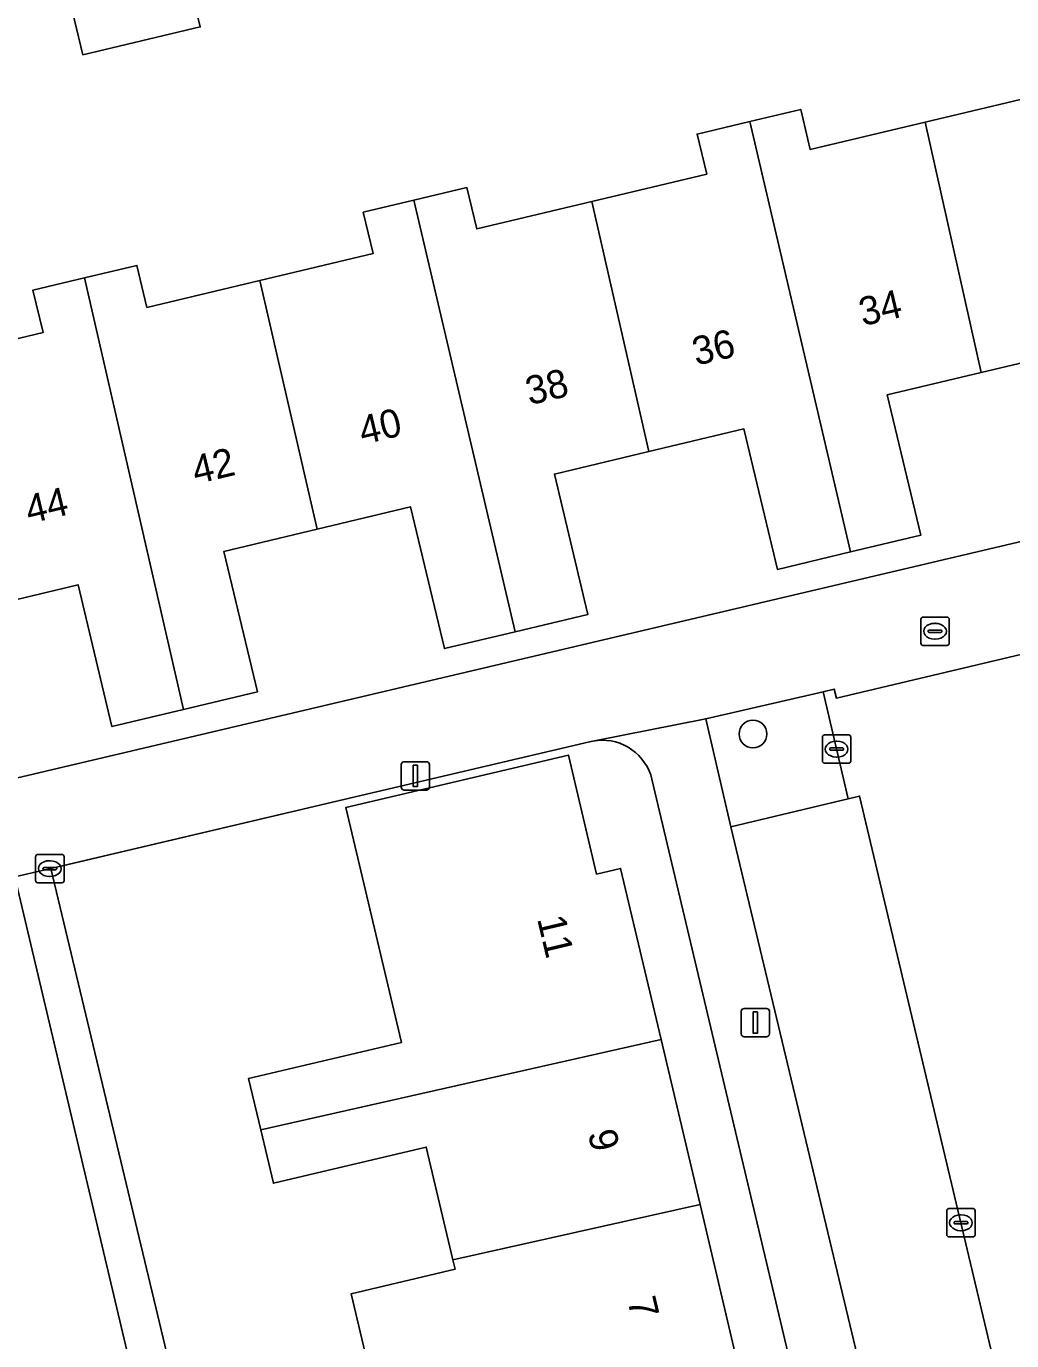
# Model space of a CAD drawing. Extents: x 158031 to 159244, y 380104 to 381214.
# Drawn here: x 158383.81 to 158418.58, y 380885.43 to 380931.84 of the extents above; entities that cross this region are included whole.
import ezdxf

# ---------------------------------------------------------------- set-up
doc = ezdxf.new("R2010")
doc.units = 0
for name, color, linetype in [('IMGEO_Boom', 7, 'Continuous'), ('IMGEO_Erf', 7, 'Continuous'), ('IMGEO_Groenvoorziening', 7, 'Continuous'), ('IMGEO_Kolk', 7, 'Continuous'), ('IMGEO_Lichtmast', 7, 'Continuous'), ('IMGEO_Muur', 7, 'Continuous'), ('IMGEO_Pand', 7, 'Continuous'), ('IMGEO_Pand_nummerreeks', 7, 'Continuous'), ('IMGEO_Parkeervlak_open', 7, 'Continuous'), ('IMGEO_Rijbaan_lokaal_open', 7, 'Continuous'), ('IMGEO_Rioolput', 7, 'Continuous'), ('IMGEO_Voetpad_open', 7, 'Continuous')]:
    doc.layers.add(name, color=color, linetype=linetype)

msp = doc.modelspace()

# ---------------------------------------------------------------- linework, layer by layer
at = {"layer": 'IMGEO_Boom'}
msp.add_circle((158409.446, 380906.85), 0.489, dxfattribs=at)
at = {"layer": 'IMGEO_Erf'}
msp.add_lwpolyline([(158385.8, 380930.828), (158385.214, 380933.284), (158389.357, 380934.271), (158389.942, 380931.815)], close=True, dxfattribs=at)
for points in [[(158380.362, 380920.062), (158384.397, 380921.024), (158384.04, 380922.522), (158385.859, 380922.955), (158387.708, 380923.396), (158388.061, 380921.914), (158392.049, 380922.864), (158396.041, 380923.815), (158395.694, 380925.272), (158397.483, 380925.698), (158399.355, 380926.144), (158399.703, 380924.684), (158403.762, 380925.651), (158407.815, 380926.617), (158407.478, 380928.032), (158409.334, 380928.474), (158411.133, 380928.903), (158411.471, 380927.486), (158415.526, 380928.452), (158419.584, 380929.419)], [(158420.824, 380920.408), (158417.502, 380919.616), (158414.185, 380918.826), (158415.366, 380913.868), (158412.889, 380913.278), (158410.309, 380912.663), (158409.128, 380917.62), (158405.771, 380916.82), (158402.444, 380916.027), (158403.625, 380911.072), (158401.054, 380910.459), (158398.557, 380909.864), (158397.364, 380914.868), (158394.068, 380914.082), (158390.781, 380913.299), (158391.963, 380908.338), (158389.354, 380907.717), (158386.828, 380907.115), (158385.635, 380912.121), (158382.383, 380911.346)], [(158371.904, 380902.569), (158443.778, 380919.513)], [(158414.344, 380869.537), (158405.883, 380905.251), (158405.838, 380905.406), (158405.78, 380905.556), (158405.708, 380905.701), (158405.624, 380905.838), (158405.528, 380905.967), (158405.421, 380906.088), (158405.303, 380906.198), (158405.176, 380906.297), (158405.041, 380906.385), (158404.898, 380906.46), (158404.749, 380906.522), (158404.596, 380906.57), (158404.438, 380906.605), (158404.278, 380906.625), (158404.117, 380906.631), (158403.956, 380906.623), (158403.797, 380906.6), (158403.676, 380906.573), (158395.014, 380904.536), (158384.676, 380902.106), (158392.784, 380868.149)], [(158396.132, 380883.458), (158395.274, 380887.088), (158398.935, 380887.953), (158398.856, 380888.287), (158397.916, 380892.265), (158392.524, 380890.99), (158392.078, 380892.879), (158391.65, 380894.688), (158397.04, 380895.962), (158395.081, 380904.254), (158402.935, 380906.109), (158403.928, 380901.906), (158404.777, 380902.106), (158406.205, 380896.065), (158407.583, 380890.235), (158408.966, 380884.383)], [(158388.286, 380881.153), (158383.406, 380901.807)]]:
    msp.add_lwpolyline(points, dxfattribs=at)
at = {"layer": 'IMGEO_Groenvoorziening'}
msp.add_lwpolyline([(158411.93, 380908.345), (158407.779, 380907.39), (158408.671, 380903.573), (158412.805, 380904.563)], close=True, dxfattribs=at)
at = {"layer": 'IMGEO_Kolk'}
for p, q in [((158411.898, 380905.891), (158411.898, 380906.743)), ((158411.973, 380906.817), (158412.825, 380906.817)), ((158412.386, 380906.597), (158412.411, 380906.597)), ((158412.899, 380906.743), (158412.899, 380905.891)), ((158412.157, 380906.311), (158412.157, 380906.323)), ((158412.595, 380906.274), (158412.197, 380906.274)), ((158412.2, 380906.36), (158412.598, 380906.36)), ((158412.641, 380906.323), (158412.641, 380906.311)), ((158412.825, 380905.817), (158411.973, 380905.817)), ((158412.409, 380906.037), (158412.384, 380906.037)), ((158384.136, 380901.671), (158384.136, 380902.523)), ((158384.211, 380902.597), (158385.063, 380902.597)), ((158384.624, 380902.377), (158384.649, 380902.377)), ((158385.137, 380902.523), (158385.137, 380901.671)), ((158384.395, 380902.091), (158384.395, 380902.103)), ((158384.833, 380902.054), (158384.435, 380902.054)), ((158384.438, 380902.14), (158384.836, 380902.14)), ((158384.879, 380902.103), (158384.879, 380902.091)), ((158385.063, 380901.597), (158384.211, 380901.597)), ((158384.647, 380901.817), (158384.622, 380901.817)), ((158416.285, 380889.169), (158416.285, 380890.021)), ((158416.36, 380890.095), (158417.212, 380890.095)), ((158416.773, 380889.875), (158416.798, 380889.875)), ((158417.286, 380890.021), (158417.286, 380889.169)), ((158416.544, 380889.589), (158416.544, 380889.601)), ((158416.982, 380889.552), (158416.584, 380889.552)), ((158416.587, 380889.638), (158416.985, 380889.638)), ((158417.028, 380889.601), (158417.028, 380889.589)), ((158417.212, 380889.095), (158416.36, 380889.095)), ((158416.796, 380889.315), (158416.771, 380889.315))]:
    msp.add_line(p, q, dxfattribs=at)
for points in [[(158411.898, 380905.891), (158411.898, 380906.743)], [(158411.973, 380906.817), (158412.825, 380906.817)], [(158412.899, 380906.743), (158412.899, 380905.891)], [(158412.825, 380905.817), (158411.973, 380905.817)], [(158384.136, 380901.671), (158384.136, 380902.523)], [(158384.211, 380902.597), (158385.063, 380902.597)], [(158385.137, 380902.523), (158385.137, 380901.671)], [(158385.063, 380901.597), (158384.211, 380901.597)], [(158416.285, 380889.169), (158416.285, 380890.021)], [(158416.36, 380890.095), (158417.212, 380890.095)], [(158417.286, 380890.021), (158417.286, 380889.169)], [(158417.212, 380889.095), (158416.36, 380889.095)]]:
    msp.add_lwpolyline(points, dxfattribs=at)
for centre, radius, start, end in [((158411.975, 380906.741), 0.0765, 91.552, 178.448), ((158411.975, 380906.741), 0.0765, 91.552, 178.448), ((158412.823, 380906.741), 0.0765, 1.552, 88.448), ((158412.823, 380906.741), 0.0765, 1.552, 88.448), ((158412.197, 380906.32), 0.0403, 85.8775, 175.7526), ((158412.194, 380906.31), 0.0366, 178.938, 274.7102), ((158412.598, 380906.317), 0.043, 264.8664, 352.4533), ((158412.602, 380906.322), 0.0386, 1.7309, 96.639), ((158411.975, 380905.893), 0.0765, 181.552, 268.448), ((158411.975, 380905.893), 0.0765, 181.552, 268.448), ((158412.823, 380905.893), 0.0765, 271.552, 358.448), ((158412.823, 380905.893), 0.0765, 271.552, 358.448), ((158384.213, 380902.521), 0.0765, 91.552, 178.448), ((158384.213, 380902.521), 0.0765, 91.552, 178.448), ((158385.061, 380902.521), 0.0765, 1.552, 88.448), ((158385.061, 380902.521), 0.0765, 1.552, 88.448), ((158384.435, 380902.1), 0.0403, 85.8775, 175.7526), ((158384.432, 380902.09), 0.0366, 178.938, 274.7102), ((158384.836, 380902.097), 0.043, 264.8664, 352.4533), ((158384.84, 380902.102), 0.0386, 1.7309, 96.639), ((158384.213, 380901.673), 0.0765, 181.552, 268.448), ((158384.213, 380901.673), 0.0765, 181.552, 268.448), ((158385.061, 380901.673), 0.0765, 271.552, 358.448), ((158385.061, 380901.673), 0.0765, 271.552, 358.448), ((158416.362, 380890.019), 0.0765, 91.552, 178.448), ((158416.362, 380890.019), 0.0765, 91.552, 178.448), ((158417.21, 380890.019), 0.0765, 1.552, 88.448), ((158417.21, 380890.019), 0.0765, 1.552, 88.448), ((158416.584, 380889.598), 0.0403, 85.8775, 175.7526), ((158416.581, 380889.588), 0.0366, 178.938, 274.7102), ((158416.985, 380889.595), 0.043, 264.8664, 352.4533), ((158416.989, 380889.6), 0.0386, 1.7309, 96.639), ((158416.362, 380889.171), 0.0765, 181.552, 268.448), ((158416.362, 380889.171), 0.0765, 181.552, 268.448), ((158417.21, 380889.171), 0.0765, 271.552, 358.448), ((158417.21, 380889.171), 0.0765, 271.552, 358.448)]:
    msp.add_arc(centre, radius, start, end, dxfattribs=at)
for centre, major_axis, ratio, start_param, end_param in [((158412.385, 380906.317), (-0.387, 0.002), 0.722429, 4.712389, 7.853982), ((158412.41, 380906.317), (-0.39, 0.002), 0.717154, 1.570796, 4.712389), ((158384.623, 380902.097), (-0.387, 0.002), 0.722429, 4.712389, 7.853982), ((158384.648, 380902.097), (-0.39, 0.002), 0.717154, 1.570796, 4.712389), ((158416.772, 380889.595), (-0.387, 0.002), 0.722429, 4.712389, 7.853982), ((158416.797, 380889.595), (-0.39, 0.002), 0.717154, 1.570796, 4.712389)]:
    msp.add_ellipse(centre, major_axis=major_axis, ratio=ratio, start_param=start_param, end_param=end_param, dxfattribs=at)
at = {"layer": 'IMGEO_Lichtmast'}
for p, q in [((158397.038, 380904.972), (158397.038, 380905.772)), ((158397.038, 380905.772), (158397.038, 380904.972)), ((158397.138, 380905.872), (158397.928, 380905.872)), ((158397.928, 380905.872), (158397.138, 380905.872)), ((158398.028, 380905.772), (158398.028, 380904.972)), ((158398.028, 380904.972), (158398.028, 380905.772)), ((158397.928, 380904.872), (158397.138, 380904.872)), ((158397.138, 380904.872), (158397.928, 380904.872)), ((158409.036, 380896.261), (158409.036, 380897.061)), ((158409.036, 380897.061), (158409.036, 380896.261)), ((158409.136, 380897.161), (158409.926, 380897.161)), ((158409.926, 380897.161), (158409.136, 380897.161)), ((158410.026, 380897.061), (158410.026, 380896.261)), ((158410.026, 380896.261), (158410.026, 380897.061)), ((158409.926, 380896.161), (158409.136, 380896.161)), ((158409.136, 380896.161), (158409.926, 380896.161))]:
    msp.add_line(p, q, dxfattribs=at)
for points in [[(158397.458, 380905.747), (158397.608, 380905.747), (158397.608, 380904.997), (158397.458, 380904.997), (158397.458, 380905.747)], [(158409.456, 380897.036), (158409.606, 380897.036), (158409.606, 380896.286), (158409.456, 380896.286), (158409.456, 380897.036)]]:
    msp.add_lwpolyline(points, dxfattribs=at)
for centre, start, end in [((158397.138, 380905.772), 90, 180), ((158397.138, 380905.772), 90, 180), ((158397.928, 380905.772), 0, 90), ((158397.928, 380905.772), 360, 90), ((158397.138, 380904.972), 180, 270), ((158397.138, 380904.972), 180, 270), ((158397.928, 380904.972), 270, 0), ((158397.928, 380904.972), 270, 0), ((158409.136, 380897.061), 90, 180), ((158409.136, 380897.061), 90, 180), ((158409.926, 380897.061), 0, 90), ((158409.926, 380897.061), 360, 90), ((158409.136, 380896.261), 180, 270), ((158409.136, 380896.261), 180, 270), ((158409.926, 380896.261), 270, 0), ((158409.926, 380896.261), 270, 0)]:
    msp.add_arc(centre, 0.1, start, end, dxfattribs=at)
at = {"layer": 'IMGEO_Muur'}
msp.add_lwpolyline([(158385.085, 380902.202), (158395.014, 380904.536)], dxfattribs=at)
at = {"layer": 'IMGEO_Pand'}
for points in [[(158385.8, 380930.828), (158389.942, 380931.815), (158389.357, 380934.271), (158385.214, 380933.284)], [(158424.583, 380916.043), (158421.005, 380931.238), (158419.25, 380930.82), (158419.584, 380929.419), (158415.526, 380928.452), (158417.502, 380919.616), (158420.824, 380920.408), (158422.011, 380915.43)], [(158409.334, 380928.474), (158412.889, 380913.278), (158415.366, 380913.868), (158414.185, 380918.826), (158417.502, 380919.616), (158415.526, 380928.452), (158411.471, 380927.486), (158411.133, 380928.903)], [(158403.762, 380925.651), (158405.771, 380916.82), (158409.128, 380917.62), (158410.309, 380912.663), (158412.889, 380913.278), (158409.334, 380928.474), (158407.478, 380928.032), (158407.815, 380926.617)], [(158401.054, 380910.459), (158403.625, 380911.072), (158402.444, 380916.027), (158405.771, 380916.82), (158403.762, 380925.651), (158399.703, 380924.684), (158399.355, 380926.144), (158397.483, 380925.698)], [(158401.054, 380910.459), (158397.483, 380925.698), (158395.694, 380925.272), (158396.041, 380923.815), (158392.049, 380922.864), (158394.068, 380914.082), (158397.364, 380914.868), (158398.557, 380909.864)], [(158392.049, 380922.864), (158388.061, 380921.914), (158387.708, 380923.396), (158385.859, 380922.955), (158389.354, 380907.717), (158391.963, 380908.338), (158390.781, 380913.299), (158394.068, 380914.082)], [(158380.362, 380920.062), (158382.383, 380911.346), (158385.635, 380912.121), (158386.828, 380907.115), (158389.354, 380907.717), (158385.859, 380922.955), (158384.04, 380922.522), (158384.397, 380921.024)], [(158392.078, 380892.879), (158406.205, 380896.065), (158404.777, 380902.106), (158403.928, 380901.906), (158402.935, 380906.109), (158395.081, 380904.254), (158397.04, 380895.962), (158391.65, 380894.688)], [(158392.078, 380892.879), (158392.524, 380890.99), (158397.916, 380892.265), (158398.856, 380888.287), (158407.583, 380890.235), (158406.205, 380896.065)], [(158407.583, 380890.235), (158398.856, 380888.287), (158398.935, 380887.953), (158395.274, 380887.088), (158396.132, 380883.458), (158394.387, 380883.045), (158394.832, 380881.163), (158408.966, 380884.383)]]:
    msp.add_lwpolyline(points, close=True, dxfattribs=at)
at = {"layer": 'IMGEO_Parkeervlak_open'}
msp.add_lwpolyline([(158408.671, 380903.573), (158417.003, 380868.676), (158421.49, 380869.778), (158413.211, 380904.66), (158412.805, 380904.563)], close=True, dxfattribs=at)
at = {"layer": 'IMGEO_Rijbaan_lokaal_open'}
msp.add_lwpolyline([(158422.216, 380891.65), (158450.904, 380898.43), (158446.846, 380916.284), (158412.391, 380908.116), (158412.316, 380908.434), (158411.93, 380908.345), (158412.805, 380904.563), (158413.211, 380904.66), (158421.49, 380869.778), (158423.115, 380862.932), (158426.327, 380849.398), (158426.008, 380849.326), (158426.87, 380845.655), (158427.196, 380845.738), (158432.809, 380847.002)], close=True, dxfattribs=at)
at = {"layer": 'IMGEO_Rioolput'}
for p, q in [((158415.371, 380910.052), (158415.371, 380910.904)), ((158415.446, 380910.978), (158416.298, 380910.978)), ((158415.859, 380910.758), (158415.884, 380910.758)), ((158416.372, 380910.904), (158416.372, 380910.052)), ((158415.63, 380910.472), (158415.63, 380910.484)), ((158416.068, 380910.435), (158415.67, 380910.435)), ((158415.673, 380910.521), (158416.071, 380910.521)), ((158416.114, 380910.484), (158416.114, 380910.472)), ((158416.298, 380909.978), (158415.446, 380909.978)), ((158415.882, 380910.198), (158415.857, 380910.198))]:
    msp.add_line(p, q, dxfattribs=at)
for points in [[(158415.371, 380910.052), (158415.371, 380910.904)], [(158415.446, 380910.978), (158416.298, 380910.978)], [(158416.372, 380910.904), (158416.372, 380910.052)], [(158416.298, 380909.978), (158415.446, 380909.978)]]:
    msp.add_lwpolyline(points, dxfattribs=at)
for centre, radius, start, end in [((158415.448, 380910.902), 0.0765, 91.552, 178.448), ((158415.448, 380910.902), 0.0765, 91.552, 178.448), ((158416.296, 380910.902), 0.0765, 1.552, 88.448), ((158416.296, 380910.902), 0.0765, 1.552, 88.448), ((158415.67, 380910.481), 0.0403, 85.8775, 175.7526), ((158415.667, 380910.471), 0.0366, 178.938, 274.7102), ((158416.071, 380910.478), 0.043, 264.8664, 352.4533), ((158416.075, 380910.483), 0.0386, 1.7309, 96.639), ((158415.448, 380910.054), 0.0765, 181.552, 268.448), ((158415.448, 380910.054), 0.0765, 181.552, 268.448), ((158416.296, 380910.054), 0.0765, 271.552, 358.448), ((158416.296, 380910.054), 0.0765, 271.552, 358.448)]:
    msp.add_arc(centre, radius, start, end, dxfattribs=at)
for centre, major_axis, ratio, start_param, end_param in [((158415.858, 380910.478), (-0.387, 0.002), 0.722429, 4.712389, 7.853982), ((158415.883, 380910.478), (-0.39, 0.002), 0.717154, 1.570796, 4.712389)]:
    msp.add_ellipse(centre, major_axis=major_axis, ratio=ratio, start_param=start_param, end_param=end_param, dxfattribs=at)
at = {"layer": 'IMGEO_Voetpad_open'}
for points in [[(158443.778, 380919.513), (158371.904, 380902.569), (158372.63, 380899.273), (158383.406, 380901.807), (158384.676, 380902.106), (158395.014, 380904.536), (158403.676, 380906.573), (158403.797, 380906.6), (158407.779, 380907.39), (158411.93, 380908.345), (158412.316, 380908.434), (158412.391, 380908.116), (158446.846, 380916.284)], [(158417.003, 380868.676), (158408.671, 380903.573), (158407.779, 380907.39), (158403.797, 380906.6), (158403.956, 380906.623), (158404.117, 380906.631), (158404.278, 380906.625), (158404.438, 380906.605), (158404.596, 380906.57), (158404.749, 380906.522), (158404.898, 380906.46), (158405.041, 380906.385), (158405.176, 380906.297), (158405.303, 380906.198), (158405.421, 380906.088), (158405.528, 380905.967), (158405.624, 380905.838), (158405.708, 380905.701), (158405.78, 380905.556), (158405.838, 380905.406), (158405.883, 380905.251), (158414.344, 380869.537)]]:
    msp.add_lwpolyline(points, dxfattribs=at)
msp.add_lwpolyline([(158392.784, 380868.149), (158384.676, 380902.106), (158383.406, 380901.807), (158388.286, 380881.153), (158388.478, 380881.198), (158388.837, 380879.679), (158388.645, 380879.634), (158392.838, 380861.888), (158382.937, 380859.549), (158378.984, 380858.615), (158374.118, 380857.465), (158371.247, 380856.787), (158371.587, 380855.347), (158375.938, 380856.375), (158384.071, 380858.296), (158407.386, 380863.784), (158413.457, 380865.266), (158413.191, 380866.551), (158413.149, 380866.686), (158408.284, 380865.536), (158404.369, 380864.611), (158396.233, 380862.775), (158394.184, 380862.286)], close=True, dxfattribs=at)

# ---------------------------------------------------------------- texts
at = {"layer": 'IMGEO_Pand_nummerreeks'}
for s, rotation, p in [('34', 13.342, (158413.324, 380921.246)), ('36', 13.342, (158407.441, 380919.85)), ('38', 13.342, (158401.561, 380918.456)), ('40', 13.342, (158395.677, 380917.061)), ('42', 13.342, (158389.788, 380915.664)), ('44', 13.342, (158383.907, 380914.269)), ('11', 283.2986, (158401.826, 380900.33)), ('9', 283.2986, (158403.615, 380892.765)), ('7', 283.2981, (158405.01, 380886.862))]:
    msp.add_text(s, height=1, rotation=rotation, dxfattribs=at).set_placement(p)

doc.saveas('drawing.dxf')
